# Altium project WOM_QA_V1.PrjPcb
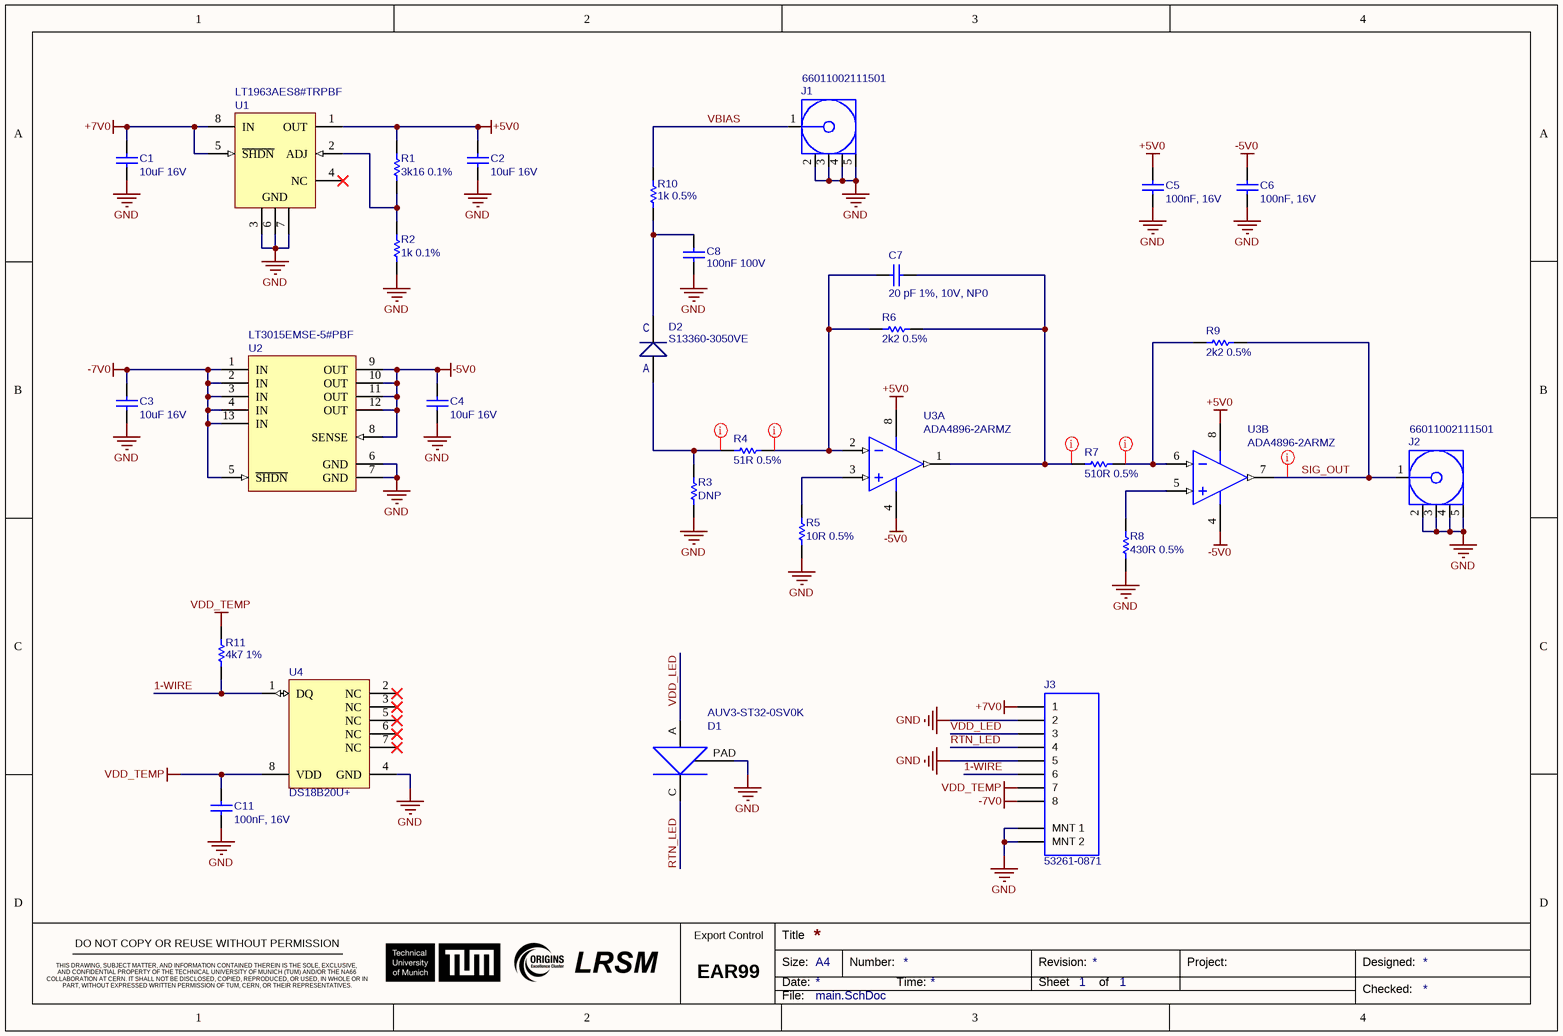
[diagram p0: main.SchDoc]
1 sheet, 29 parts. Net scope: global (net labels, ports and power ports of the same name join across sheets).
Board files: WOM_QA_V1.PcbDoc, WOM_QA_V2.PcbDoc

## Sheet main.SchDoc
size A4; SheetNumber: 1; SheetTotal: 1

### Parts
C1  10uF 16V  [WCAP-CSGP_1206_H=1.6mm]
C2  10uF 16V  [WCAP-CSGP_1206_H=1.6mm]
C3  10uF 16V  [WCAP-CSGP_1206_H=1.6mm]
C4  10uF 16V  [WCAP-CSGP_1206_H=1.6mm]
C5  100nF, 16V  [WCAP-CSGP_0402_H=0.5mm]
C6  100nF, 16V  [WCAP-CSGP_0402_H=0.5mm]
C7  20 pF 1%, 10V, NP0  [WCAP-CSGP_0402_H=0.5mm]
C8  100nF 100V  [WCAP-CSGP_0603_H=0.8mm_Reflow]
C11  100nF, 16V  [WCAP-CSGP_0402_H=0.5mm]
D1  AUV3-ST32-0SV0K  [AUV3-ST32-0SV0K-Footprint-1]
D2  S13360-3050VE  [S13360-3050VE-Footprint-1]
J1  66011002111501  [66011002111501]
J2  66011002111501  [66011002111501]
J3  53261-0871  [FP-532610871-MFG]
R1  3k16 0.1%  [RESC0402(1005)_N]
R2  1k 0.1%  [RESC0402(1005)_N]
R3  DNP  [RESC0402(1005)_N]
R4  51R 0.5%  [RESC0402(1005)_N]
R5  10R 0.5%  [RESC0402(1005)_N]
R6  2k2 0.5%  [RESC0402(1005)_N]
R7  510R 0.5%  [RESC0402(1005)_N]
R8  430R 0.5%  [RESC0402(1005)_N]
R9  2k2 0.5%  [RESC0402(1005)_N]
R10  1k 0.5%  [RESC0603(1608)_N]
R11  4k7 1%  [RESC0402(1005)_N]
U1  LT1963AES8#TRPBF  [SOIC127P600X175-8N]
U2  LT3015EMSE-5#PBF  [TSOP65P490X110_HS-13N]
U3  ADA4896-2ARMZ  [TSOP65P490X110-8N]  (parts A,B of 2)
U4  DS18B20U+  [MAXM-U8+1_V]

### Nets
+5V0: C2.2 C5.2 R1.2 U1.1(OUT) U3.8(+VS)
+7V0: C1.2 J3.1 U1.5(~{SHDN}) U1.8(IN)
-5V0: C4.2 C6.2 U2.8(SENSE) U2.9(OUT) U2.10(OUT) U2.11(OUT) U2.12(OUT) U3.4(-VS)
-7V0: C3.2 J3.8 U2.1(IN) U2.2(IN) U2.3(IN) U2.4(IN) U2.5(~{SHDN}) U2.13(IN)
GND: C1.1 C2.1 C3.1 C4.1 C5.1 C6.1 C8.1 C11.1 D1.PAD J1.2(GND) J1.3(GND) J1.4(GND) J1.5(GND) J2.2(GND) J2.3(GND) J2.4(GND) J2.5(GND) J3.2 J3.5 J3.9(MNT_1) J3.10(MNT_2) R2.1 R3.1 R5.1 R8.1 U1.3(GND) U1.6(GND) U1.7(GND) U2.6(GND) U2.7(GND) U4.4(GND)
VDD_TEMP: C11.2 J3.7 R11.2 U4.8(VDD)
1-WIRE: J3.6 R11.1 U4.1(DQ)
RTN_LED: D1.C J3.4
SIG_OUT: J2.1(Signal) R9.2 U3.7(OUT_2)
VBIAS: J1.1(Signal) R10.2
VDD_LED: D1.A J3.3
NetC7_1: C7.1 R4.1 R6.1 U3.2(-IN_1)
NetC7_2: C7.2 R6.2 R7.1 U3.1(OUT_1)
NetC8_2: C8.2 D2.2(C) R10.1
NetD2_1: D2.1(A) R3.2 R4.2
NetR1_1: R1.1 R2.2 U1.2(ADJ)
NetR5_2: R5.2 U3.3(+IN_1)
NetR7_2: R7.2 R9.1 U3.6(-IN_2)
NetR8_2: R8.2 U3.5(+IN_2)

Not connected (* = marked no-connect by the designer): U1 4(NC)*; U4 2(NC)* 3(NC)* 5(NC)* 6(NC)* 7(NC)*

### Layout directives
net class S50: NetC7_1, NetC7_2, NetD2_1, NetR7_2, SIG_OUT

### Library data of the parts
C1-C4 = CMP-010-0785-1: WCAP-CSGP Multilayer Ceramic Chip Capacitor, General Purpose, size 1206, X7R, 10uF, 16V; Manufacturer: Wurth Elektronik; Manufacturer Part Number: 885012208041; Capacitance Tolerance: +/-10%; Technical Reference: X7R1206106K016DFCT10000; Rated Voltage: 16VDC; Isolation Resistance: >=0.01GOhm; Value: 10µF
C5 C6 C11 = CMP-010-0480-1: WCAP-CSGP Multilayer Ceramic Chip Capacitor, General Purpose, size 0402, X7R, 100nF, 16V; Manufacturer Part Number: 885012205037; Manufacturer: Wurth Elektronik; Rated Voltage: 16VDC; Isolation Resistance: >=5GOhm; Technical Reference: X7R0402104K016DFCT10000; Capacitance Tolerance: +/-10%
C7 = CMP-010-0006-1: WCAP-CSGP Multilayer Ceramic Chip Capacitor, General Purpose, size 0402, NP0, 10pF, 10V; Manufacturer: Wurth Elektronik; Manufacturer Part Number: 885012005007; Dissipation Factor: Q>=400+20C; Rated Voltage: 10VDC; Capacitance Tolerance: +/-5%; Isolation Resistance: >=10GOhm; Technical Reference: NP00402100J010DFCT10000
C8 = CMP-010-0623-1: WCAP-CSGP Multilayer Ceramic Chip Capacitor, General Purpose, size 0603, X7R, 100nF, 100V; Manufacturer Part Number: 885012206120; Manufacturer: Wurth Elektronik; Technical Reference: X7R0603104K100DFCT10000; Isolation Resistance: >=1GOhm; Rated Voltage: 100VDC; Capacitance Tolerance: +/-10%
D1 = CMP-00285-1
D2 = CMP-00090-1: MPPC for precision measurement
J1 J2 = CMP-002-00434-1: WR-MMCX PCB Jack, THT, Right Angle, 6GHz, 50O; Manufacturer: Wurth Elektronik; Center Contact Diameter: 0.7mm; Connector Type: MMCX; Interface Type: IEC 61169-52
J3 = CMP-002-00452-2: 1.25mm (.049") Pitch PicoBlade Header, Surface Mount, Right Angle, Lead-free, 8 Circuits; Gender: Male
R1 = CMP-015-0047-1: Res Thin Film 0402 3.16K Ohm 0.1% 1/16W ±25ppm/°C Molded SMD Punched Carrier T/R; Resistance: 3.16kR; Voltage Rating: 25V; Max Power Dissipation: 63mW; Voltage Rating (DC): 50V
R2 = CMP-009-00196-1: Voltage Rating: 25V; Voltage Rating (DC): 50V; Resistance: 1kR; Max Power Dissipation: 63mW; Temperature Coefficient: 25ppm/°C
R3 = CMP-009-00205-1: Max Power Dissipation: 63mW; Temperature Coefficient: 25ppm/°C; Tolerance: 0.5%; Power Rating: 62.5mW; Resistance: 51R
R4 = CMP-009-00205-1: Max Power Dissipation: 63mW; Temperature Coefficient: 25ppm/°C; Power Rating: 62.5mW
R5 = CMP-015-0063-1: Res, 10R, 0.5%, 0.1W, 0402 Rohs Compliant: Yes; Max Power Dissipation: 100mW; Voltage Rating (DC): 50V; Temperature Coefficient: 200ppm/°C; Tolerance: 5%
R6 R9 = CMP-015-0062-1: Res, 2K2, 0.5%, 0.1W, 0402 Rohs Compliant: Yes; Temperature Coefficient: 100ppm/°C; Resistance: 2kR; Power Rating: 100mW; Voltage Rating (DC): 50V; Resistance Tolerance: 1%
R7 = CMP-015-0064-1: Resistance Tolerance: 1%; Voltage Rating (DC): 50V; Resistance: 523R; Temperature Coefficient: 100ppm/°C; Max Power Dissipation: 100mW
R8 = CMP-015-0065-1: Res Thick Film 0402 430 Ohm 0.5% 0.063W(1/16W) ±50ppm/C Pad SMD Automotive T/R; Power Rating: 63mW; Voltage Rating: 50V; Temperature Coefficient: 50ppm/°C; Max Power Dissipation: 100mW
R10 = CMP-015-0043-1: Res Thick Film 0603 1K Ohm 0.5% 0.063W ±50ppm/°C Molded SMD Punched Carrier T/R; Power Rating: 100mW; Voltage Rating: 75V; Resistance: 1kR
R11 = CMP-009-00213-1: Power Rating: 100mW; Voltage Rating (DC): 50V; Temperature Coefficient: 100ppm/°C; Resistance: 4.7kR
U1 = CMP-00189-1: IC REG LDO ADJ 1.5A 8SOIC
U2 = CMP-00188-1: LT3015 - 1.5A, Low Noise, Negative Linear Regulator with Precision Current Limit
U3 = CMP-00187-1: Op Amp Dual Low Power Amplifier R-R O/P ±5V/10V 8-Pin MSOP Tube
U4 = CMP-019-00016-2: Programmable Resolution 1-Wire Digital Thermometer, -55 to 125 degC, 8-Pin SOP, RoHS, Tube; Manufacturer: Maxim; Max Supply Voltage (DC): 5V; Max Supply Voltage: 5.5V; Output Current: 4mA; Min Supply Voltage: 3V; Nominal Supply Current: 1mA; Interface: Serial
